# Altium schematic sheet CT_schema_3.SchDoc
size 398 x 262 mm
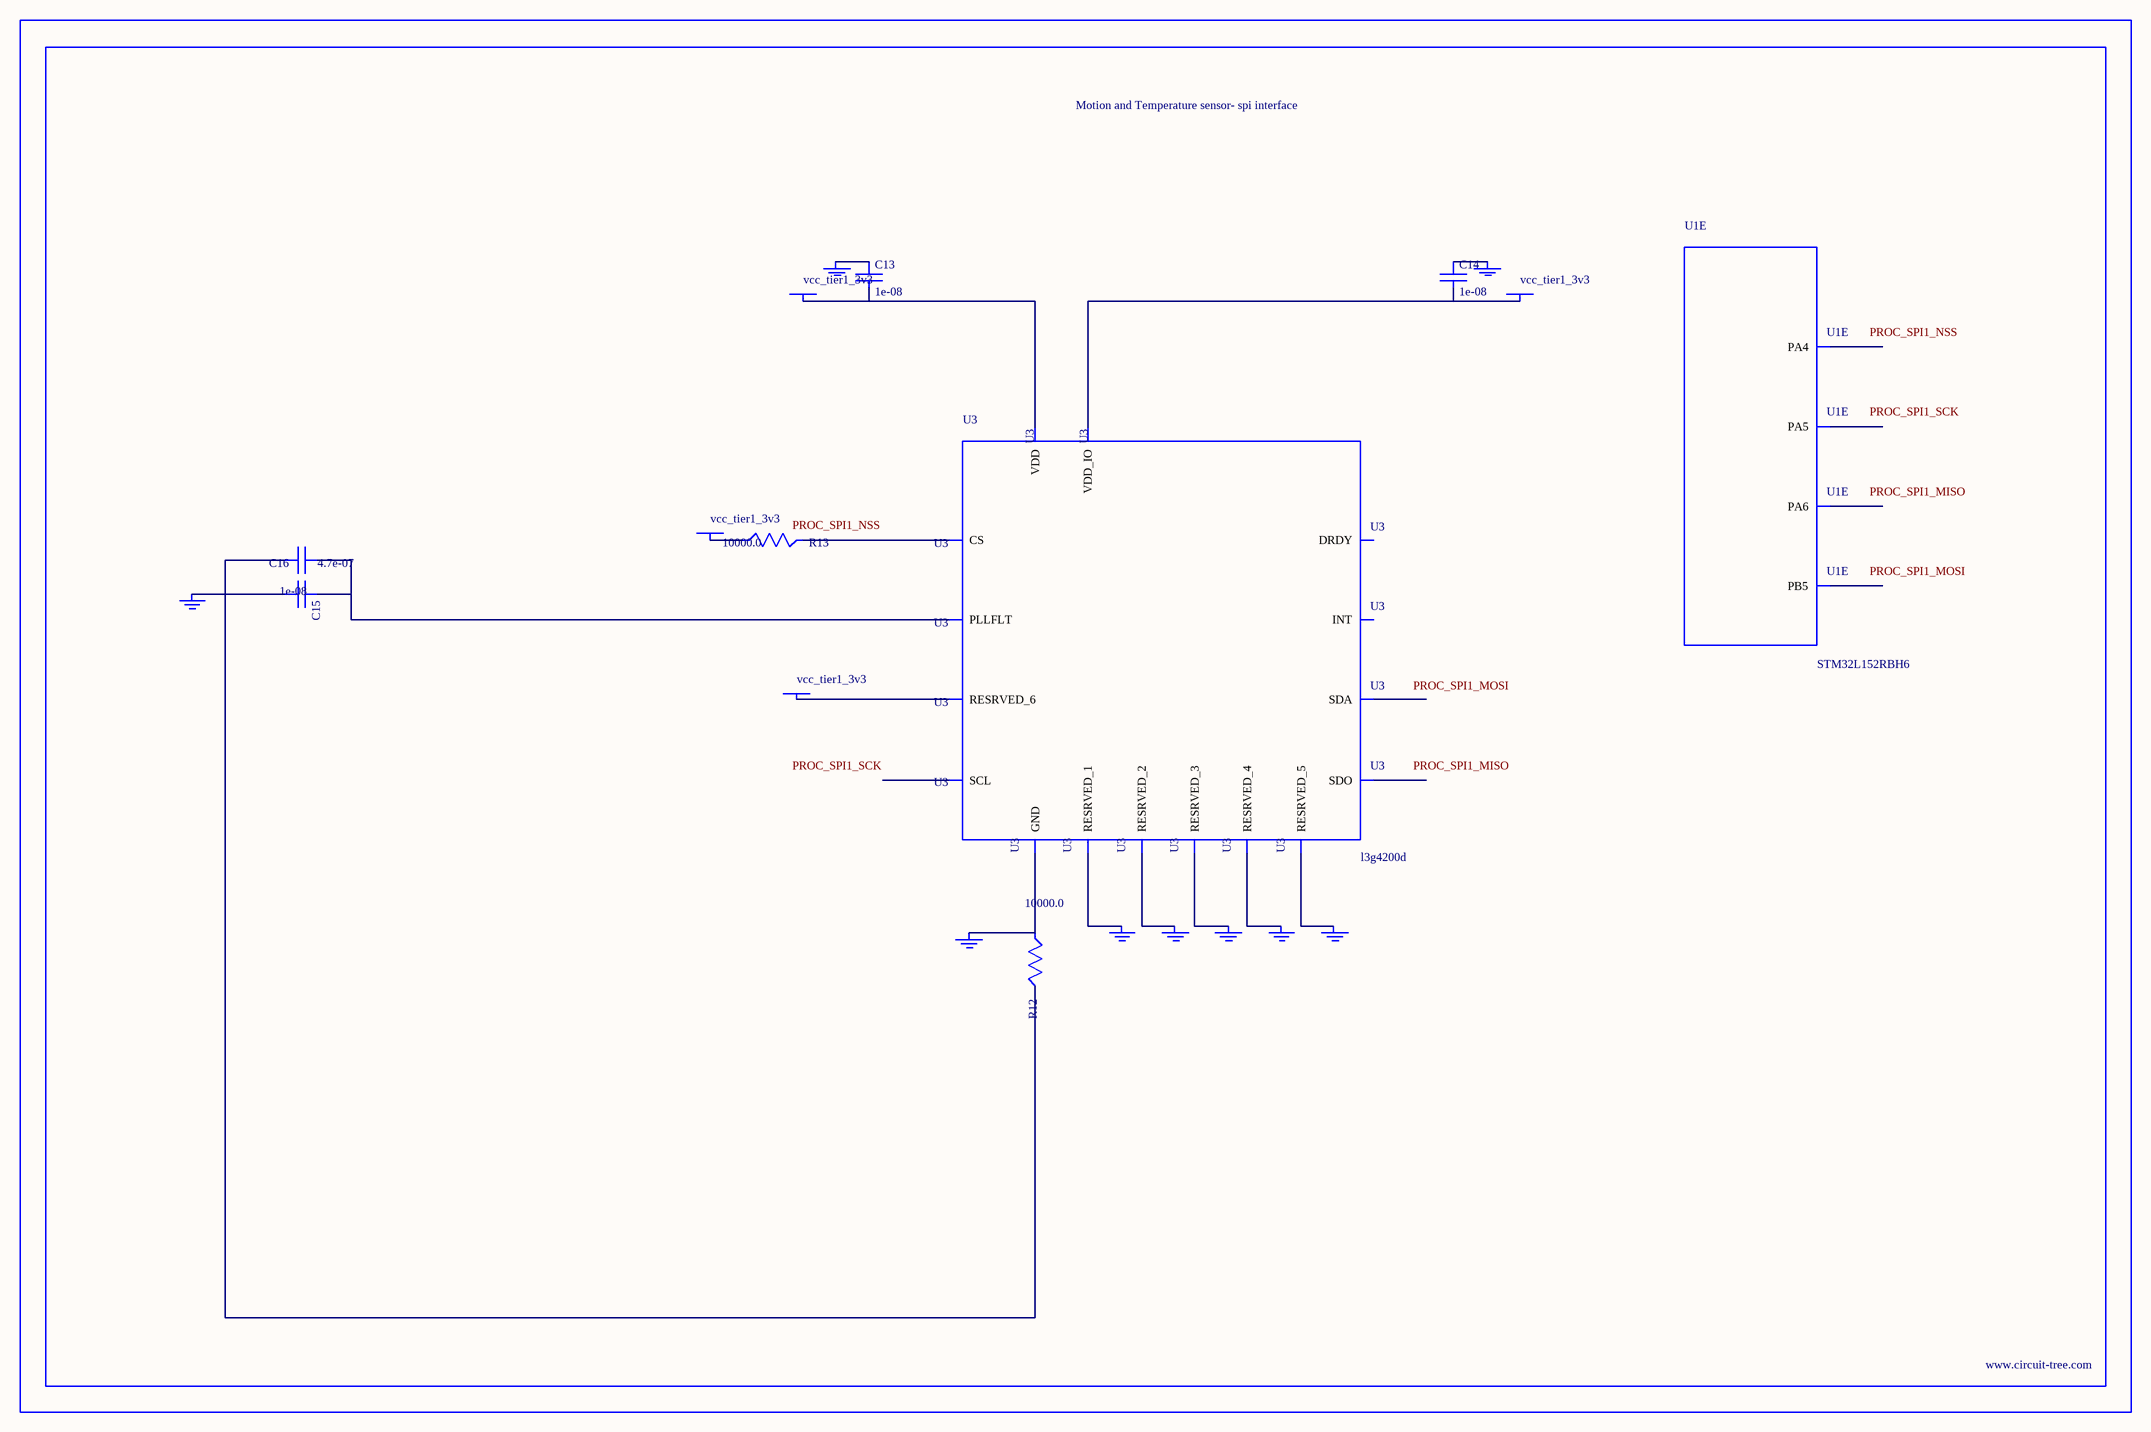
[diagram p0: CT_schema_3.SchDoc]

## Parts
BORDER2  (no value)
C13  1e-08  [C0402]
C14  1e-08  [C0402]
C15  1e-08  [C0402]
C16  4.7e-07  [C0603]
GND_INSTANCE_2_0  (no value)
GND_INSTANCE_2_1  (no value)
GND_INSTANCE_2_2  (no value)
GND_INSTANCE_2_3  (no value)
GND_INSTANCE_2_4  (no value)
GND_INSTANCE_2_5  (no value)
GND_INSTANCE_2_6  (no value)
GND_INSTANCE_2_7  (no value)
GND_INSTANCE_2_8  (no value)
POWER_INSTANCE_2_0  vcc_tier1_3v3
POWER_INSTANCE_2_1  vcc_tier1_3v3
POWER_INSTANCE_2_2  vcc_tier1_3v3
POWER_INSTANCE_2_3  vcc_tier1_3v3
R12  10000.0  [R0603]
R13  10000.0  [R0603]
U1  STM32L152RBH6  [TFBGA64]  (part E of 7)
U3  l3g4200d  [LGA-16]

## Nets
NetC13_1: C13.1 GND_INSTANCE_2_8.0(GND)
NetC13_2: C13.2 POWER_INSTANCE_2_3.0(PWR) U3.16(VDD)
NetC14_1: C14.1 GND_INSTANCE_2_0.0(GND)
NetC14_2: C14.2 POWER_INSTANCE_2_0.0(PWR) U3.1(VDD_IO)
NetC15_1: C15.1 C16.1 U3.14(PLLFLT)
NetC15_2: C15.2 C16.2 GND_INSTANCE_2_7.0(GND) R12.2
NetGND_INSTANCE_2_1_0: GND_INSTANCE_2_1.0(GND) U3.8(RESRVED_1)
NetGND_INSTANCE_2_2_0: GND_INSTANCE_2_2.0(GND) U3.9(RESRVED_2)
NetGND_INSTANCE_2_3_0: GND_INSTANCE_2_3.0(GND) U3.10(RESRVED_3)
NetGND_INSTANCE_2_4_0: GND_INSTANCE_2_4.0(GND) U3.11(RESRVED_4)
NetGND_INSTANCE_2_5_0: GND_INSTANCE_2_5.0(GND) U3.12(RESRVED_5)
NetGND_INSTANCE_2_6_0: GND_INSTANCE_2_6.0(GND) R12.1 U3.13(GND)
NetPOWER_INSTANCE_2_1_0: POWER_INSTANCE_2_1.0(PWR) R13.1
NetPOWER_INSTANCE_2_2_0: POWER_INSTANCE_2_2.0(PWR) U3.15(RESRVED_6)
NetR13_2: R13.2 U3.5(CS)

Not connected (* = marked no-connect by the designer): U1 C4(PB5) F4(PA5) G4(PA6) H3(PA4); U3 2(SCL) 3(SDA) 4(SDO) 6(DRDY) 7(INT)

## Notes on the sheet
- Labels drawn without touching a wire or pin: PROC_SPI1_MISO, PROC_SPI1_MOSI, PROC_SPI1_NSS, PROC_SPI1_SCK

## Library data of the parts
BORDER2 = BORDER_PAGE2
C13-C15 = C0402C103K3RAC
C16 = C0603C474K3RAC
GND_INSTANCE_2_0-GND_INSTANCE_2_8 = GND
POWER_INSTANCE_2_0-POWER_INSTANCE_2_3 = PWR
R12 R13 = RC0603JR-0710KL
